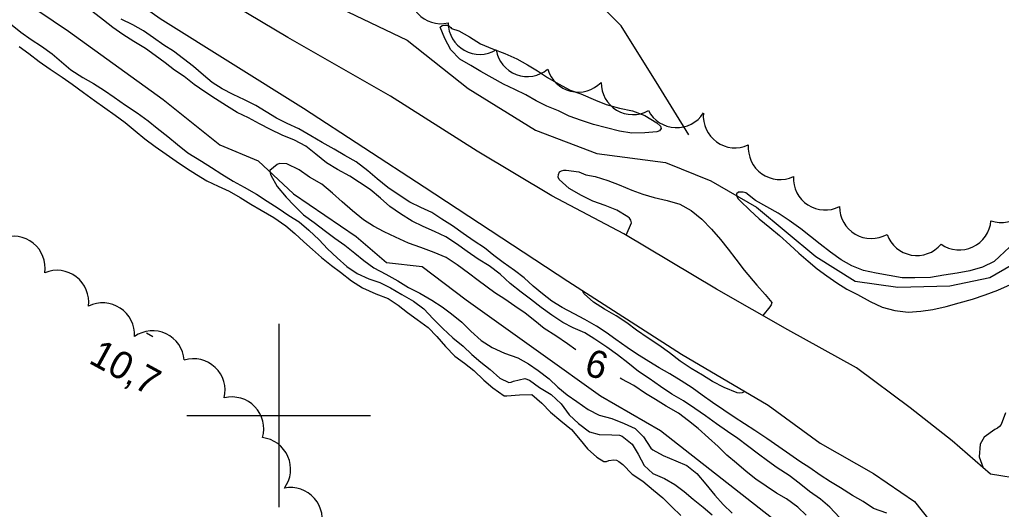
# Model space of a CAD drawing. Extents: x 219136 to 222520, y 5421589 to 5424530.
# Drawn here: x 221571.8 to 221678.7, y 5423389.8 to 5423443.2 of the extents above; entities that cross this region are included whole.
import ezdxf

# ---------------------------------------------------------------- set-up
doc = ezdxf.new("R2010")
doc.units = 0
for name, color, linetype in [('Level 1', 7, 'Continuous'), ('Level 19', 7, 'Continuous'), ('Level 2', 7, 'Continuous'), ('Level 22', 7, 'Continuous'), ('Level 3', 7, 'Continuous'), ('Level 4', 7, 'Continuous'), ('Level 44', 7, 'Continuous'), ('Level 61', 7, 'Continuous')]:
    doc.layers.add(name, color=color, linetype=linetype)

msp = doc.modelspace()

# ---------------------------------------------------------------- linework, layer by layer
at = {"layer": 'Level 1'}
for points in [[(221602.2, 5423431.24), (221600.91, 5423431.82), (221599.77, 5423432.43), (221598.63, 5423433.1), (221597.49, 5423433.79), (221596.28, 5423434.42), (221595.04, 5423435.01), (221593.85, 5423435.6), (221592.76, 5423436.3), (221591.79, 5423437.12), (221590.7, 5423438.03), (221589.63, 5423438.9), (221588.53, 5423439.72), (221587.47, 5423440.39), (221586.34, 5423441.16), (221585.26, 5423441.93), (221584.09, 5423442.58), (221582.83, 5423443.2)], [(221571.73, 5423440.22), (221572.77, 5423439.46), (221573.89, 5423438.61), (221575.11, 5423437.75), (221576.41, 5423436.87), (221577.48, 5423436.13), (221578.73, 5423435.21), (221579.92, 5423434.33), (221581.05, 5423433.54), (221582.16, 5423432.75), (221583.28, 5423431.93), (221584.34, 5423431.05), (221585.4, 5423430.17), (221586.55, 5423429.33), (221587.72, 5423428.48), (221588.81, 5423427.71), (221589.95, 5423426.97), (221591.05, 5423426.26), (221592.17, 5423425.58), (221593.41, 5423424.99), (221594.6, 5423424.45), (221595.8, 5423423.76), (221596.96, 5423423.03), (221598.09, 5423422.39), (221599.48, 5423421.57), (221600.76, 5423420.68), (221601.74, 5423419.83), (221602.72, 5423418.95), (221603.66, 5423418.08), (221604.64, 5423417.24), (221605.73, 5423416.37)], [(221666.23, 5423389.36), (221664.8, 5423389.87), (221663.65, 5423390.61), (221662.51, 5423391.29), (221661.2, 5423392.13), (221660.12, 5423392.78), (221658.99, 5423393.48), (221657.86, 5423394.31), (221656.78, 5423394.98), (221655.67, 5423395.74), (221654.49, 5423396.6), (221653.16, 5423397.51), (221651.88, 5423398.38), (221650.75, 5423399.09), (221649.61, 5423399.81), (221648.49, 5423400.58), (221647.25, 5423401.42), (221646.11, 5423402.2), (221645.03, 5423403.01), (221643.83, 5423403.79), (221642.62, 5423404.54), (221641.44, 5423405.21), (221640.33, 5423405.87), (221638.99, 5423406.74), (221637.95, 5423407.43), (221636.73, 5423408.27), (221635.67, 5423409.03), (221634.63, 5423409.74), (221633.33, 5423410.45), (221632.17, 5423411.09), (221630.86, 5423411.79), (221629.74, 5423412.47), (221628.72, 5423413.26), (221627.73, 5423414.11), (221626.73, 5423414.99), (221625.69, 5423415.81), (221624.43, 5423416.69), (221623.42, 5423417.46), (221622.41, 5423418.28), (221621.28, 5423418.99), (221620.08, 5423419.84), (221618.94, 5423420.67), (221617.78, 5423421.4), (221616.66, 5423422.13), (221615.46, 5423422.69), (221614.28, 5423423.27), (221613.1, 5423424.01), (221611.87, 5423424.85), (221610.73, 5423425.79), (221609.69, 5423426.66), (221608.43, 5423427.64), (221607.18, 5423428.35), (221606.03, 5423429.04), (221604.74, 5423429.77), (221603.48, 5423430.5), (221602.2, 5423431.24)], [(221679.61, 5423418.34), (221678.53, 5423417.34), (221677.95, 5423416.79), (221676.68, 5423416.16), (221675.3, 5423415.76), (221673.92, 5423415.51), (221672.44, 5423415.29), (221670.99, 5423415.06), (221669.3, 5423415), (221667.92, 5423415.01), (221666.49, 5423415.26), (221665.09, 5423415.52), (221663.71, 5423415.82), (221662.44, 5423416.3), (221661.28, 5423416.96), (221660.12, 5423417.82), (221658.97, 5423418.66), (221657.92, 5423419.52), (221656.86, 5423420.36), (221655.59, 5423421.27), (221654.39, 5423422.07), (221653.16, 5423422.74), (221651.93, 5423423.43), (221650.88, 5423424.28), (221650.6, 5423424.34), (221650.07, 5423424.33), (221649.88, 5423424.15), (221649.92, 5423423.87), (221650.05, 5423423.62), (221650.25, 5423423.4), (221651.33, 5423422.4), (221652.35, 5423421.45), (221653.5, 5423420.51), (221654.54, 5423419.61), (221655.68, 5423418.59), (221656.64, 5423417.71), (221657.67, 5423416.81), (221658.65, 5423416)], [(221605.73, 5423416.37), (221606.73, 5423415.61), (221607.94, 5423414.69), (221609.14, 5423413.92), (221610.56, 5423413.25), (221611.91, 5423412.76), (221613.02, 5423412.03), (221614.01, 5423411.23), (221615.09, 5423410.47), (221616.26, 5423409.6), (221617.21, 5423408.61), (221618.16, 5423407.51), (221619.18, 5423406.48), (221620.22, 5423405.69), (221621.24, 5423404.91), (221622.35, 5423403.84), (221623.32, 5423403), (221624.57, 5423402.16), (221624.86, 5423402.14), (221626.21, 5423402.24), (221627.56, 5423402.3), (221628.66, 5423401.34), (221629.6, 5423400.36), (221630.73, 5423399.41), (221631.9, 5423398.48), (221632.85, 5423397.33), (221633.64, 5423396.36), (221634.65, 5423395.46), (221635.4, 5423394.98), (221635.69, 5423395), (221635.97, 5423395.09), (221636.51, 5423395.18), (221636.81, 5423395.12), (221637.06, 5423395), (221637.5, 5423394.64), (221638.5, 5423393.61), (221639.67, 5423392.85), (221640.82, 5423391.87), (221641.83, 5423391.01), (221642.82, 5423390.05), (221643.81, 5423389.09)], [(221658.65, 5423416), (221659.7, 5423415.22), (221660.78, 5423414.47), (221661.9, 5423413.76), (221663.06, 5423413.19), (221664.41, 5423412.44), (221665.73, 5423411.81), (221667.13, 5423411.45), (221668.55, 5423411.28), (221669.95, 5423411.36), (221671.27, 5423411.56), (221672.69, 5423411.88), (221674.12, 5423412.27), (221675.59, 5423412.68), (221676.96, 5423413.17), (221678.32, 5423413.68), (221679.7, 5423414.29)], [(221679.17, 5423400.29), (221678.69, 5423399.02), (221678.51, 5423398.81), (221678.29, 5423398.63), (221678.01, 5423398.49), (221676.84, 5423397.64), (221676.4, 5423396.89), (221676.3, 5423395.48), (221676.74, 5423394.31)]]:
    msp.add_lwpolyline(points, dxfattribs=at)
at = {"layer": 'Level 19'}
for points in [[(221697.93, 5423388.98), (221697.06, 5423396.18), (221695.69, 5423399.65), (221693.13, 5423399.24), (221689.89, 5423396.84), (221685.7, 5423394.25), (221681.13, 5423393.01), (221677.55, 5423393.6), (221673.37, 5423397.25), (221668.77, 5423400.83), (221662.95, 5423405.21), (221655.46, 5423409.35), (221647.69, 5423413.76), (221637.61, 5423419.79), (221629.74, 5423423.94), (221621.6, 5423428.8), (221612.16, 5423434.82), (221601, 5423441.22), (221589.52, 5423448.07), (221579.16, 5423455.01), (221566.87, 5423463.74)], [(221570.47, 5423455.09), (221587.08, 5423443.28), (221602.7, 5423433.51), (221615.85, 5423424.93), (221631.48, 5423414.64), (221643.87, 5423406.7), (221653.31, 5423401.14), (221658.98, 5423396.97), (221664.8, 5423393.67), (221669.24, 5423390.63), (221672.47, 5423386.58)]]:
    msp.add_lwpolyline(points, dxfattribs=at)
at = {"layer": 'Level 2'}
for points in [[(221621.74, 5423417.03), (221620.51, 5423417.89), (221619.36, 5423418.73), (221618.21, 5423419.48), (221616.95, 5423420.06), (221615.73, 5423420.62), (221614.55, 5423421.17), (221613.27, 5423422), (221612.11, 5423422.78), (221611.07, 5423423.68), (221609.96, 5423424.62), (221608.78, 5423425.41), (221607.73, 5423426.09), (221606.39, 5423426.8), (221605.19, 5423427.54), (221604.05, 5423428.5), (221602.96, 5423429.37), (221601.7, 5423430.03), (221600.36, 5423430.57), (221599.1, 5423431.19), (221597.89, 5423431.8), (221596.7, 5423432.46), (221595.48, 5423433.05), (221594.3, 5423433.76), (221593.09, 5423434.51), (221591.96, 5423435.27), (221590.79, 5423436.1), (221589.7, 5423436.95), (221588.65, 5423437.64), (221587.61, 5423438.44), (221586.52, 5423439.26), (221585.47, 5423440.02), (221584.22, 5423440.79), (221583.01, 5423441.55), (221581.92, 5423442.29), (221580.89, 5423443.11), (221579.65, 5423444.08)], [(221570.77, 5423442.71), (221571.89, 5423441.8), (221573.02, 5423441), (221574.15, 5423440.25), (221575.32, 5423439.41), (221576.32, 5423438.55), (221577.33, 5423437.68), (221578.64, 5423436.84), (221579.8, 5423436.18), (221581.03, 5423435.42), (221582.08, 5423434.71), (221583.3, 5423433.84), (221584.57, 5423433), (221585.79, 5423432.14), (221586.77, 5423431.31), (221587.91, 5423430.42), (221588.98, 5423429.53), (221590.08, 5423428.64), (221591.59, 5423427.71), (221592.68, 5423427.02), (221593.79, 5423426.32), (221595.02, 5423425.54), (221596.24, 5423424.88), (221597.56, 5423424.13), (221598.72, 5423423.35), (221599.95, 5423422.59), (221601.11, 5423421.82), (221602.21, 5423421.1), (221603.29, 5423420.21), (221604.39, 5423419.14), (221605.31, 5423418.16), (221606.36, 5423417.17), (221607.4, 5423416.26), (221608.54, 5423415.48), (221609.81, 5423414.89), (221611, 5423414.5), (221612.19, 5423413.91), (221613.39, 5423413.19), (221614.67, 5423412.45), (221615.79, 5423411.62), (221616.81, 5423410.53), (221617.88, 5423409.48), (221618.96, 5423408.47), (221620.08, 5423407.56), (221621.05, 5423406.66), (221622.01, 5423405.82), (221623.04, 5423405.01), (221624.1, 5423404.08), (221625.06, 5423403.59)], [(221619.6, 5423441.95), (221620.79, 5423441.27), (221621.99, 5423440.52), (221623.28, 5423439.99), (221624.62, 5423439.46), (221625.93, 5423438.87), (221627.1, 5423438.24), (221628.17, 5423437.56), (221629.26, 5423436.85), (221630.46, 5423436.14), (221631.74, 5423435.47), (221632.92, 5423435.05), (221634.52, 5423434.36), (221635.68, 5423433.89), (221637.12, 5423433.5), (221638.52, 5423433.2), (221639.87, 5423432.69), (221641.19, 5423431.9), (221641.59, 5423431.53), (221641.66, 5423431.28), (221641.47, 5423431.05), (221641.18, 5423430.94), (221639.88, 5423430.82), (221638.48, 5423430.79), (221637.12, 5423431.01), (221635.72, 5423431.37), (221634.3, 5423431.73), (221632.98, 5423432.15), (221631.65, 5423432.65), (221630.49, 5423433.21), (221629.22, 5423433.73), (221628.05, 5423434.32), (221626.91, 5423434.95), (221625.71, 5423435.53), (221624.48, 5423436.12), (221623.24, 5423436.8), (221622.01, 5423437.5), (221620.92, 5423438.15), (221619.72, 5423438.84), (221618.73, 5423439.85), (221618.09, 5423441.09), (221617.57, 5423442.35), (221617.79, 5423442.52), (221618.04, 5423442.56), (221618.31, 5423442.56), (221618.55, 5423442.46), (221618.74, 5423442.3), (221618.82, 5423442.19), (221619.6, 5423441.95)], [(221606.91, 5423423.29), (221605.86, 5423424.23), (221604.71, 5423425.23), (221603.36, 5423426), (221602.21, 5423426.78), (221600.89, 5423427.45), (221600.09, 5423427.47), (221599.84, 5423427.35), (221599.02, 5423426.71), (221599.05, 5423426.45), (221599.13, 5423426.2), (221599.81, 5423424.95), (221600.81, 5423423.81), (221601.66, 5423422.88), (221602.71, 5423421.86), (221603.87, 5423421.05), (221605.09, 5423420.11), (221606.12, 5423419.34), (221607.21, 5423418.56), (221608.29, 5423417.68), (221609.26, 5423416.88), (221610.36, 5423416.1), (221611.65, 5423415.4), (221612.97, 5423414.67), (221614.13, 5423413.95), (221615.36, 5423413.34), (221616.66, 5423412.58), (221617.79, 5423411.83), (221618.81, 5423411.1), (221619.95, 5423410.16), (221620.94, 5423409.2), (221622.06, 5423408.18), (221623.24, 5423407.4), (221624.61, 5423406.78), (221626.03, 5423406.29), (221627.22, 5423405.64), (221628.26, 5423404.9), (221629.46, 5423403.98), (221630.4, 5423403.1), (221631.41, 5423402.27), (221632.46, 5423401.54), (221633.71, 5423400.67), (221634.92, 5423400.05), (221636.27, 5423399.66), (221637.64, 5423399.14), (221638.84, 5423398.57), (221639.74, 5423397.69), (221640.54, 5423396.45), (221640.75, 5423396.25), (221641.86, 5423395.63), (221643.27, 5423395.05), (221644.47, 5423394.56), (221645.54, 5423393.67), (221646.53, 5423392.52), (221647.49, 5423391.32), (221648.43, 5423390.3), (221649.41, 5423389.36)], [(221637.83, 5423419.66), (221638.44, 5423421.02), (221638.36, 5423421.29), (221638.2, 5423421.5), (221638.01, 5423421.67), (221636.84, 5423422.38), (221635.57, 5423422.89), (221634.21, 5423423.37), (221632.98, 5423423.98), (221631.62, 5423424.74), (221630.53, 5423425.73), (221630.45, 5423426), (221630.47, 5423426.28), (221630.58, 5423426.55), (221630.79, 5423426.69), (221631.07, 5423426.75), (221631.32, 5423426.75), (221632.68, 5423426.55), (221633.45, 5423426.25), (221633.45, 5423426.25), (221634.46, 5423426.05)], [(221634.46, 5423426.05), (221635.86, 5423425.61), (221637.09, 5423425.13), (221638.45, 5423424.58), (221639.68, 5423424.12), (221640.89, 5423423.77), (221642.33, 5423423.44), (221643.69, 5423423.04), (221644.94, 5423422.35), (221646.09, 5423421.39), (221647.13, 5423420.32), (221648.13, 5423419.19), (221648.97, 5423418.14), (221649.81, 5423417.03), (221650.7, 5423415.85), (221652.07, 5423414.21), (221652.99, 5423413.19), (221653.72, 5423412.31), (221653.63, 5423412.06), (221653.49, 5423411.83), (221652.72, 5423410.91)], [(221632.38, 5423407.16), (221631.44, 5423407.83), (221630.18, 5423408.69), (221628.93, 5423409.48), (221627.89, 5423410.32), (221626.84, 5423411.16), (221625.73, 5423411.92), (221624.63, 5423412.68), (221623.53, 5423413.37), (221621.72, 5423414.7), (221620.67, 5423415.52), (221619.44, 5423416.43), (221618.24, 5423417.21), (221616.93, 5423417.78), (221615.49, 5423418.32), (221614.13, 5423418.8), (221612.71, 5423419.43), (221611.48, 5423420.02), (221610.33, 5423420.64), (221609.22, 5423421.34), (221608.02, 5423422.33), (221606.91, 5423423.29)], [(221661.09, 5423388.89), (221660.04, 5423390.01), (221659.02, 5423390.89), (221657.81, 5423391.71), (221656.71, 5423392.62), (221655.6, 5423393.45), (221654.29, 5423394.31), (221653.26, 5423395.07), (221652.25, 5423395.8), (221651.08, 5423396.7), (221650.01, 5423397.51), (221648.87, 5423398.24), (221647.68, 5423399.1), (221646.49, 5423399.95), (221645.33, 5423400.78), (221644.11, 5423401.59), (221642.83, 5423402.34), (221641.6, 5423403.17), (221640.37, 5423404.02), (221639.18, 5423404.8), (221638.04, 5423405.73), (221636.91, 5423406.6), (221635.74, 5423407.45), (221634.43, 5423408.31), (221633.36, 5423409.02), (221632.08, 5423409.56), (221630.95, 5423410.14), (221629.74, 5423410.95), (221628.57, 5423411.78), (221627.41, 5423412.7), (221626.39, 5423413.44), (221625.21, 5423414.4), (221624.13, 5423415.39), (221622.91, 5423416.31), (221621.74, 5423417.03)], [(221643.73, 5423405.94), (221642.58, 5423406.84), (221641.41, 5423407.66), (221640.25, 5423408.44), (221638.98, 5423409.31), (221637.91, 5423410.09), (221636.74, 5423410.85), (221635.49, 5423411.61), (221634.3, 5423412.35), (221633.27, 5423413.28), (221633.1, 5423413.6)], [(221650.79, 5423402.63), (221650.5, 5423402.47), (221650.24, 5423402.44), (221649.94, 5423402.48), (221648.51, 5423403.05), (221647.25, 5423403.69), (221646.16, 5423404.39), (221644.91, 5423405.12), (221643.73, 5423405.94)], [(221625.06, 5423403.59), (221625.31, 5423403.64), (221625.58, 5423403.75), (221626.8, 5423404.04), (221627.32, 5423403.85), (221628.41, 5423403.04), (221629.66, 5423402.29), (221630.77, 5423401.28), (221631.64, 5423400.07), (221632.67, 5423399.12), (221633.86, 5423398.22), (221634.9, 5423397.92), (221636.27, 5423397.9), (221637.13, 5423397.86), (221637.41, 5423397.74), (221638.51, 5423396.88), (221639.14, 5423395.79), (221639.79, 5423394.56), (221640.74, 5423393.69), (221642.04, 5423393.14), (221643.13, 5423392.48), (221644.17, 5423391.73), (221645.15, 5423390.89), (221646.22, 5423390.01), (221647.23, 5423389.18)], [(221657.46, 5423389.12), (221656.53, 5423390.02), (221655.33, 5423390.92), (221654.21, 5423391.53), (221653.09, 5423392.28), (221651.98, 5423393.07), (221650.92, 5423393.89), (221649.86, 5423394.79), (221648.82, 5423395.67), (221647.86, 5423396.61), (221646.81, 5423397.58), (221645.68, 5423398.57), (221644.62, 5423399.43), (221643.56, 5423400.27), (221642.22, 5423401.03), (221641.06, 5423401.73), (221639.97, 5423402.4), (221638.67, 5423403.27), (221637.38, 5423403.95), (221637.2, 5423404.06)]]:
    msp.add_lwpolyline(points, dxfattribs=at)
at = {"layer": 'Level 22'}
msp.add_lwpolyline([(221644.66, 5423430.61), (221641.41, 5423435.92), (221637.31, 5423442.47), (221633.05, 5423446.77), (221628.7, 5423451.35), (221624.28, 5423457.87), (221617.15, 5423466.5), (221612.04, 5423474.57), (221605.81, 5423483.21), (221599.48, 5423490.15), (221593.95, 5423496.87), (221588.36, 5423500.55), (221584.16, 5423506.15), (221578.25, 5423513.28), (221574.97, 5423518.3), (221573.69, 5423522.48), (221573.05, 5423527.13), (221572.22, 5423531.11), (221570.68, 5423533.56)], dxfattribs=at)
at = {"layer": 'Level 3'}
msp.add_line((221585.58, 5423409), (221586.29, 5423408.61), dxfattribs=at)
at = {"layer": 'Level 4'}
for points in [[(221478.31, 5423509.24), (221488.02, 5423502.98), (221499.5, 5423495.61), (221509.34, 5423489.82), (221520.32, 5423482.18), (221534.09, 5423473.12), (221544.85, 5423465.85), (221554.97, 5423457.75), (221566.8, 5423448.85), (221577.09, 5423441.89), (221587.4, 5423434.46), (221593.59, 5423429.5), (221597.77, 5423427.78), (221601.6, 5423424.16), (221608.43, 5423419.5), (221611.75, 5423416.69), (221615.63, 5423416.23), (221620.4, 5423412.6), (221628.56, 5423406.8), (221635.06, 5423402.15), (221641.59, 5423398.38), (221653.68, 5423388.88)], [(221568.21, 5423465.65), (221577.96, 5423458.87), (221586.59, 5423453.18), (221593.1, 5423449.43), (221601.14, 5423447.1), (221613.98, 5423440.93), (221620.65, 5423435.65), (221627.98, 5423431.11), (221634.66, 5423428.57), (221642.14, 5423427.59), (221647.07, 5423425.57), (221652.03, 5423422.71), (221658.5, 5423417.33), (221662.8, 5423414.65), (221667.44, 5423414), (221673.09, 5423414.14), (221677.48, 5423415.06), (221681.41, 5423417.33)]]:
    msp.add_lwpolyline(points, dxfattribs=at)
at = {"layer": 'Level 44'}
for centre, start, end in [((221617.67, 5423446.17), 162.9224, 282.9224), ((221621.91, 5423442.83), 180.567, 300.567), ((221627.09, 5423440.42), 189.5297, 309.5297), ((221632.62, 5423438.71), 196.1702, 316.1702), ((221638.58, 5423436.26), 179.1499, 299.1499), ((221643.34, 5423434.84), 207.5075, 327.5075), ((221649.71, 5423432.64), 174.5128, 294.5128), ((221654.6, 5423429.19), 174.9453, 294.9453), ((221659.52, 5423425.86), 176.9999, 296.9999), ((221678.7, 5423424.5), 251.3325, 11.3325), ((221664.56, 5423422.75), 179.4671, 299.4671), ((221674.14, 5423421.51), 235.2244, 355.2244), ((221571.09, 5423416.09), 351.2509, 111.2509), ((221669.52, 5423420.9), 199.747, 319.747), ((221575.84, 5423412.37), 352.5227, 112.5227), ((221580.83, 5423408.82), 356.6056, 116.6056), ((221586.26, 5423405.77), 4.7253, 124.7253), ((221590.7, 5423402.73), 346.605, 106.605), ((221594.9, 5423398.56), 343.7482, 103.7482), ((221597.83, 5423394.15), 323.5164, 83.5164), ((221601.28, 5423388.69), 341.0845, 101.0845)]:
    msp.add_arc(centre, 3.46, start, end, dxfattribs=at)
at = {"layer": 'Level 61'}
for points in [[(221600, 5423410), (221600, 5423400), (221600, 5423390)], [(221590, 5423400), (221600, 5423400), (221610, 5423400)]]:
    msp.add_lwpolyline(points, dxfattribs=at)

# ---------------------------------------------------------------- texts
at = {"layer": 'Level 2'}
msp.add_text('6', height=3, rotation=343.4195, dxfattribs=at).set_placement((221633.15, 5423404.48))
at = {"layer": 'Level 3'}
msp.add_text('10,7', height=3, rotation=331.383, dxfattribs=at).set_placement((221579.17, 5423405.79))

doc.saveas('drawing.dxf')
